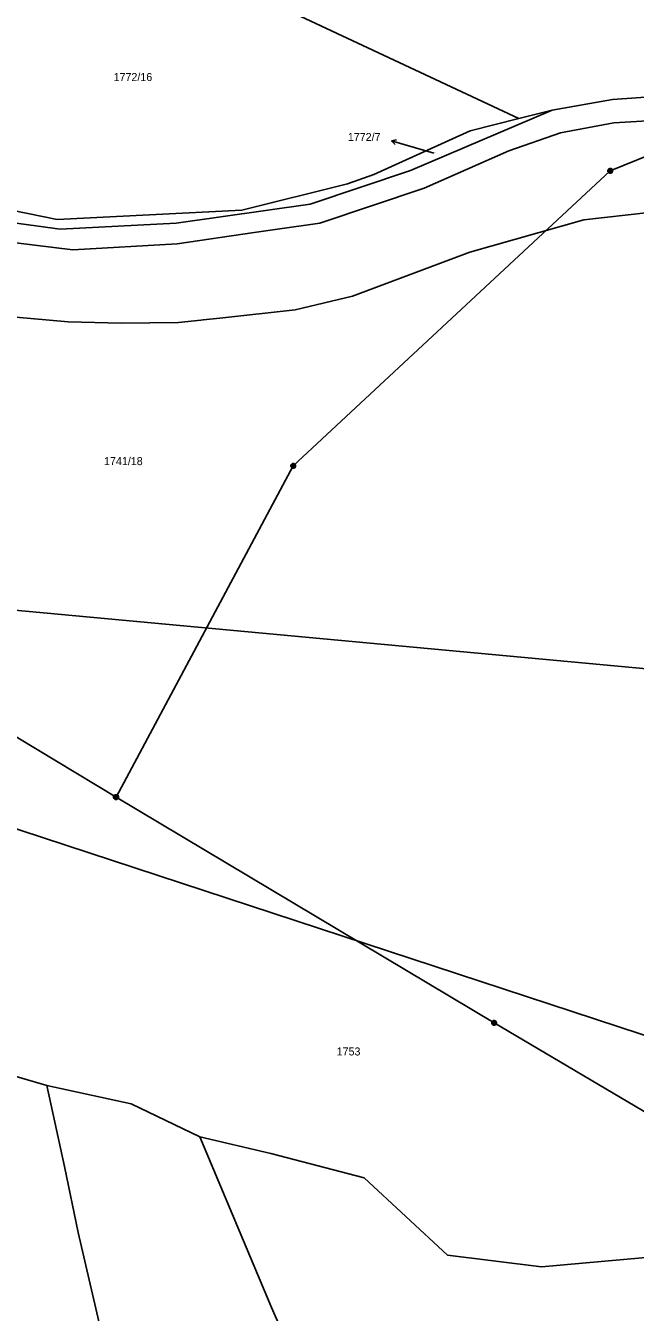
# Model space of a CAD drawing. Extents: x -795483 to -789093, y -1112258 to -1108741.
# Drawn here: x -793351.3 to -793221.7, y -1110577.6 to -1110304.3 of the extents above; entities that cross this region are included whole.
import ezdxf

# ---------------------------------------------------------------- set-up
doc = ezdxf.new("R2010")
doc.units = 0
for name, color, linetype in [('Komunikace', 7, 'Continuous'), ('Vrstva 1', 7, 'Continuous'), ('Vrstva 12', 7, 'Continuous'), ('Vrstva 14', 7, 'Continuous'), ('Vrstva 16', 7, 'Continuous'), ('Vrstva 26', 7, 'Continuous')]:
    doc.layers.add(name, color=color, linetype=linetype)

msp = doc.modelspace()

# ---------------------------------------------------------------- linework, layer by layer
at = {"layer": 'Komunikace'}
msp.add_line((-793264.54, -1110331.4), (-793270.67, -1110329.62), dxfattribs=at)
at = {"layer": 'Vrstva 1'}
for p, q in [((-793369.69, -1110266.25), (-793246.46, -1110324.04)), ((-793226.61, -1110320), (-793239.39, -1110322.28)), ((-793208.75, -1110318.74), (-793226.61, -1110320)), ((-793269.48, -1110335.04), (-793239.39, -1110322.28)), ((-793246.46, -1110324.04), (-793239.39, -1110322.28)), ((-793256.85, -1110326.63), (-793246.46, -1110324.04)), ((-793237.66, -1110327.04), (-793226.29, -1110324.94)), ((-793226.29, -1110324.94), (-793208.44, -1110323.86)), ((-793277.28, -1110335.88), (-793256.85, -1110326.63)), ((-793248.59, -1110330.85), (-793237.66, -1110327.04)), ((-793266.61, -1110338.82), (-793248.59, -1110330.85)), ((-793269.48, -1110335.04), (-793290.83, -1110342.21)), ((-793282.88, -1110337.91), (-793277.28, -1110335.88)), ((-793305.31, -1110343.51), (-793282.88, -1110337.91)), ((-793288.76, -1110346.23), (-793266.61, -1110338.82)), ((-793371.09, -1110340.12), (-793344.58, -1110345.46)), ((-793290.83, -1110342.21), (-793319.29, -1110346.27)), ((-793343.95, -1110347.53), (-793369.16, -1110344.1)), ((-793344.58, -1110345.46), (-793305.31, -1110343.51)), ((-793218.88, -1110344), (-793232.68, -1110345.56)), ((-793319.29, -1110346.27), (-793343.95, -1110347.53)), ((-793298.29, -1110347.62), (-793302.72, -1110348.26)), ((-793298.29, -1110347.62), (-793288.76, -1110346.23)), ((-793232.68, -1110345.56), (-793256.86, -1110352.42)), ((-793368.28, -1110348.67), (-793341.26, -1110351.89)), ((-793319.1, -1110350.65), (-793302.72, -1110348.26)), ((-793341.26, -1110351.89), (-793319.1, -1110350.65)), ((-793256.86, -1110352.42), (-793281.8, -1110361.79)), ((-793281.8, -1110361.79), (-793294, -1110364.63)), ((-793363.01, -1110365.31), (-793342.28, -1110367.24)), ((-793314.09, -1110366.85), (-793318.8, -1110367.34)), ((-793313.58, -1110366.8), (-793314.09, -1110366.85)), ((-793309.99, -1110366.46), (-793313.58, -1110366.8)), ((-793309.99, -1110366.46), (-793294, -1110364.63)), ((-793330.95, -1110367.47), (-793342.28, -1110367.24)), ((-793330.95, -1110367.47), (-793318.8, -1110367.34)), ((-793205.35, -1110442.23), (-793497.2, -1110415.14)), ((-793358.6, -1110473.21), (-793214.47, -1110520.52)), ((-793346.75, -1110529.4), (-793375.32, -1110521.08)), ((-793346.75, -1110529.4), (-793343.02, -1110546.62)), ((-793346.75, -1110529.4), (-793328.85, -1110533.3)), ((-793314.3, -1110540.3), (-793328.85, -1110533.3)), ((-793299.01, -1110576.6), (-793314.3, -1110540.3)), ((-793314.3, -1110540.3), (-793299.21, -1110543.84)), ((-793279.33, -1110549.04), (-793299.21, -1110543.84)), ((-793343.02, -1110546.62), (-793340.13, -1110560.67)), ((-793261.65, -1110565.47), (-793279.33, -1110549.04)), ((-793333.65, -1110588.31), (-793340.13, -1110560.67)), ((-793189.78, -1110563.28), (-793241.7, -1110567.94)), ((-793261.65, -1110565.47), (-793241.7, -1110567.94)), ((-793299.01, -1110576.6), (-793289.22, -1110598.79))]:
    msp.add_line(p, q, dxfattribs=at)
at = {"layer": 'Vrstva 12'}
for p, q in [((-793227.05, -1110335.14), (-793153.99, -1110305.41)), ((-793294.41, -1110397.81), (-793227.05, -1110335.14)), ((-793332.08, -1110468.15), (-793294.41, -1110397.81)), ((-793402.18, -1110425.94), (-793332.08, -1110468.15)), ((-793332.08, -1110468.15), (-793251.74, -1110516.12)), ((-793251.74, -1110516.12), (-793163.94, -1110567.91))]:
    msp.add_line(p, q, dxfattribs=at)
at = {"layer": 'Vrstva 16'}
for p, q in [((-793273.55, -1110328.78), (-793272.45, -1110328.58)), ((-793270.67, -1110329.62), (-793273.55, -1110328.78)), ((-793273.55, -1110328.78), (-793272.73, -1110329.54))]:
    msp.add_line(p, q, dxfattribs=at)
at = {"layer": 'Vrstva 26'}
for p, q in [((-793227.55, -1110335.04), (-793227.45, -1110334.84)), ((-793227.55, -1110335.24), (-793227.55, -1110335.04)), ((-793227.45, -1110335.44), (-793227.55, -1110335.24)), ((-793227.45, -1110334.84), (-793227.35, -1110334.74)), ((-793227.35, -1110335.54), (-793227.45, -1110335.44)), ((-793227.35, -1110334.74), (-793227.15, -1110334.64)), ((-793227.35, -1110334.94), (-793227.35, -1110335.34)), ((-793227.35, -1110335.34), (-793227.15, -1110335.44)), ((-793227.15, -1110335.64), (-793227.35, -1110335.54)), ((-793227.15, -1110334.64), (-793226.95, -1110334.64)), ((-793227.15, -1110335.44), (-793227.15, -1110334.84)), ((-793227.15, -1110334.84), (-793226.95, -1110334.84)), ((-793226.95, -1110335.64), (-793227.15, -1110335.64)), ((-793226.95, -1110334.64), (-793226.75, -1110334.74)), ((-793226.95, -1110334.84), (-793226.95, -1110335.44)), ((-793226.95, -1110335.44), (-793226.75, -1110335.34)), ((-793226.75, -1110335.54), (-793226.95, -1110335.64)), ((-793226.75, -1110334.74), (-793226.65, -1110334.84)), ((-793226.75, -1110335.34), (-793226.75, -1110334.94)), ((-793226.65, -1110335.44), (-793226.75, -1110335.54)), ((-793226.65, -1110334.84), (-793226.55, -1110335.04)), ((-793226.55, -1110335.24), (-793226.65, -1110335.44)), ((-793226.55, -1110335.04), (-793226.55, -1110335.24)), ((-793294.91, -1110397.71), (-793294.81, -1110397.51)), ((-793294.91, -1110397.91), (-793294.91, -1110397.71)), ((-793294.81, -1110398.11), (-793294.91, -1110397.91)), ((-793294.81, -1110397.51), (-793294.71, -1110397.41)), ((-793294.71, -1110398.21), (-793294.81, -1110398.11)), ((-793294.71, -1110397.41), (-793294.51, -1110397.31)), ((-793294.71, -1110397.61), (-793294.71, -1110398.01)), ((-793294.71, -1110398.01), (-793294.51, -1110398.11)), ((-793294.51, -1110398.31), (-793294.71, -1110398.21)), ((-793294.51, -1110397.31), (-793294.31, -1110397.31)), ((-793294.51, -1110398.11), (-793294.51, -1110397.51)), ((-793294.51, -1110397.51), (-793294.31, -1110397.51)), ((-793294.31, -1110398.31), (-793294.51, -1110398.31)), ((-793294.31, -1110397.31), (-793294.11, -1110397.41)), ((-793294.31, -1110397.51), (-793294.31, -1110398.11)), ((-793294.31, -1110398.11), (-793294.11, -1110398.01)), ((-793294.11, -1110398.21), (-793294.31, -1110398.31)), ((-793294.11, -1110397.41), (-793294.01, -1110397.51)), ((-793294.11, -1110398.01), (-793294.11, -1110397.61)), ((-793294.01, -1110398.11), (-793294.11, -1110398.21)), ((-793294.01, -1110397.51), (-793293.91, -1110397.71)), ((-793293.91, -1110397.91), (-793294.01, -1110398.11)), ((-793293.91, -1110397.71), (-793293.91, -1110397.91)), ((-793332.58, -1110468.05), (-793332.48, -1110467.85)), ((-793332.48, -1110467.85), (-793332.38, -1110467.75)), ((-793332.38, -1110467.75), (-793332.18, -1110467.65)), ((-793332.38, -1110467.95), (-793332.38, -1110468.35)), ((-793332.18, -1110467.65), (-793331.98, -1110467.65)), ((-793332.18, -1110468.45), (-793332.18, -1110467.85)), ((-793332.18, -1110467.85), (-793331.98, -1110467.85)), ((-793331.98, -1110467.65), (-793331.78, -1110467.75)), ((-793331.98, -1110467.85), (-793331.98, -1110468.45)), ((-793331.78, -1110467.75), (-793331.68, -1110467.85)), ((-793331.78, -1110468.35), (-793331.78, -1110467.95)), ((-793331.68, -1110467.85), (-793331.58, -1110468.05)), ((-793332.58, -1110468.25), (-793332.58, -1110468.05)), ((-793332.48, -1110468.45), (-793332.58, -1110468.25)), ((-793332.38, -1110468.55), (-793332.48, -1110468.45)), ((-793332.38, -1110468.35), (-793332.18, -1110468.45)), ((-793332.18, -1110468.65), (-793332.38, -1110468.55)), ((-793331.98, -1110468.65), (-793332.18, -1110468.65)), ((-793331.98, -1110468.45), (-793331.78, -1110468.35)), ((-793331.78, -1110468.55), (-793331.98, -1110468.65)), ((-793331.68, -1110468.45), (-793331.78, -1110468.55)), ((-793331.58, -1110468.25), (-793331.68, -1110468.45)), ((-793331.58, -1110468.05), (-793331.58, -1110468.25)), ((-793252.24, -1110516.02), (-793252.14, -1110515.82)), ((-793252.24, -1110516.22), (-793252.24, -1110516.02)), ((-793252.14, -1110516.42), (-793252.24, -1110516.22)), ((-793252.14, -1110515.82), (-793252.04, -1110515.72)), ((-793252.04, -1110516.52), (-793252.14, -1110516.42)), ((-793252.04, -1110515.72), (-793251.84, -1110515.62)), ((-793252.04, -1110515.92), (-793252.04, -1110516.32)), ((-793252.04, -1110516.32), (-793251.84, -1110516.42)), ((-793251.84, -1110516.62), (-793252.04, -1110516.52)), ((-793251.84, -1110515.62), (-793251.64, -1110515.62)), ((-793251.84, -1110516.42), (-793251.84, -1110515.82)), ((-793251.84, -1110515.82), (-793251.64, -1110515.82)), ((-793251.64, -1110516.62), (-793251.84, -1110516.62)), ((-793251.64, -1110515.62), (-793251.44, -1110515.72)), ((-793251.64, -1110515.82), (-793251.64, -1110516.42)), ((-793251.64, -1110516.42), (-793251.44, -1110516.32)), ((-793251.44, -1110516.52), (-793251.64, -1110516.62)), ((-793251.44, -1110515.72), (-793251.34, -1110515.82)), ((-793251.44, -1110516.32), (-793251.44, -1110515.92)), ((-793251.34, -1110516.42), (-793251.44, -1110516.52)), ((-793251.34, -1110515.82), (-793251.24, -1110516.02)), ((-793251.24, -1110516.22), (-793251.34, -1110516.42)), ((-793251.24, -1110516.02), (-793251.24, -1110516.22))]:
    msp.add_line(p, q, dxfattribs=at)

# ---------------------------------------------------------------- texts
at = {"layer": 'Vrstva 14'}
for s, height, p in [('1772/16', 1.7, (-793332.6, -1110316.06)), ('1772/7', 0.1, (-793264.54, -1110331.4)), ('1741/18', 1.7, (-793334.63, -1110397.65)), ('1753', 1.7, (-793285.2, -1110523.04))]:
    msp.add_text(s, height=height, dxfattribs=at).set_placement(p)
at = {"layer": 'Vrstva 16'}
msp.add_text('1772/7', height=1.7, dxfattribs=at).set_placement((-793282.82, -1110328.79))

doc.saveas('drawing.dxf')
